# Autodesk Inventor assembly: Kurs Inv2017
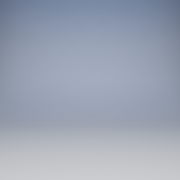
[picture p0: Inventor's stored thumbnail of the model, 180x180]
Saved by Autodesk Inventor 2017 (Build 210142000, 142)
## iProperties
Created: 2010-03
Part Number: Kurs Inv2017
Document SubType Name: Assembly
Designer: Johan Wedeen
Manufacturer: Standard
Standards Organization: Custom
Author: Johan Wedeen
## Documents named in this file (1)
- C:\Users\Public\Documents\Autodesk\Inventor 2017\Templates\InventorKurs\Kurs Inv2017.iam
